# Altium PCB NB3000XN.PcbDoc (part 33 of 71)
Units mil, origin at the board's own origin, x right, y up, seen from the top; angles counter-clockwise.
Board outline 9527.56 x 6929.77 mil, 6 copper layers (Top Layer, GND+SHIELD, MidLayer1, MidLayer2, P2 - 3V3+5V0, Bottom Layer), stack 62.375 mil thick; 832 components, 1027 nets, 4655 pads, 4981 vias.
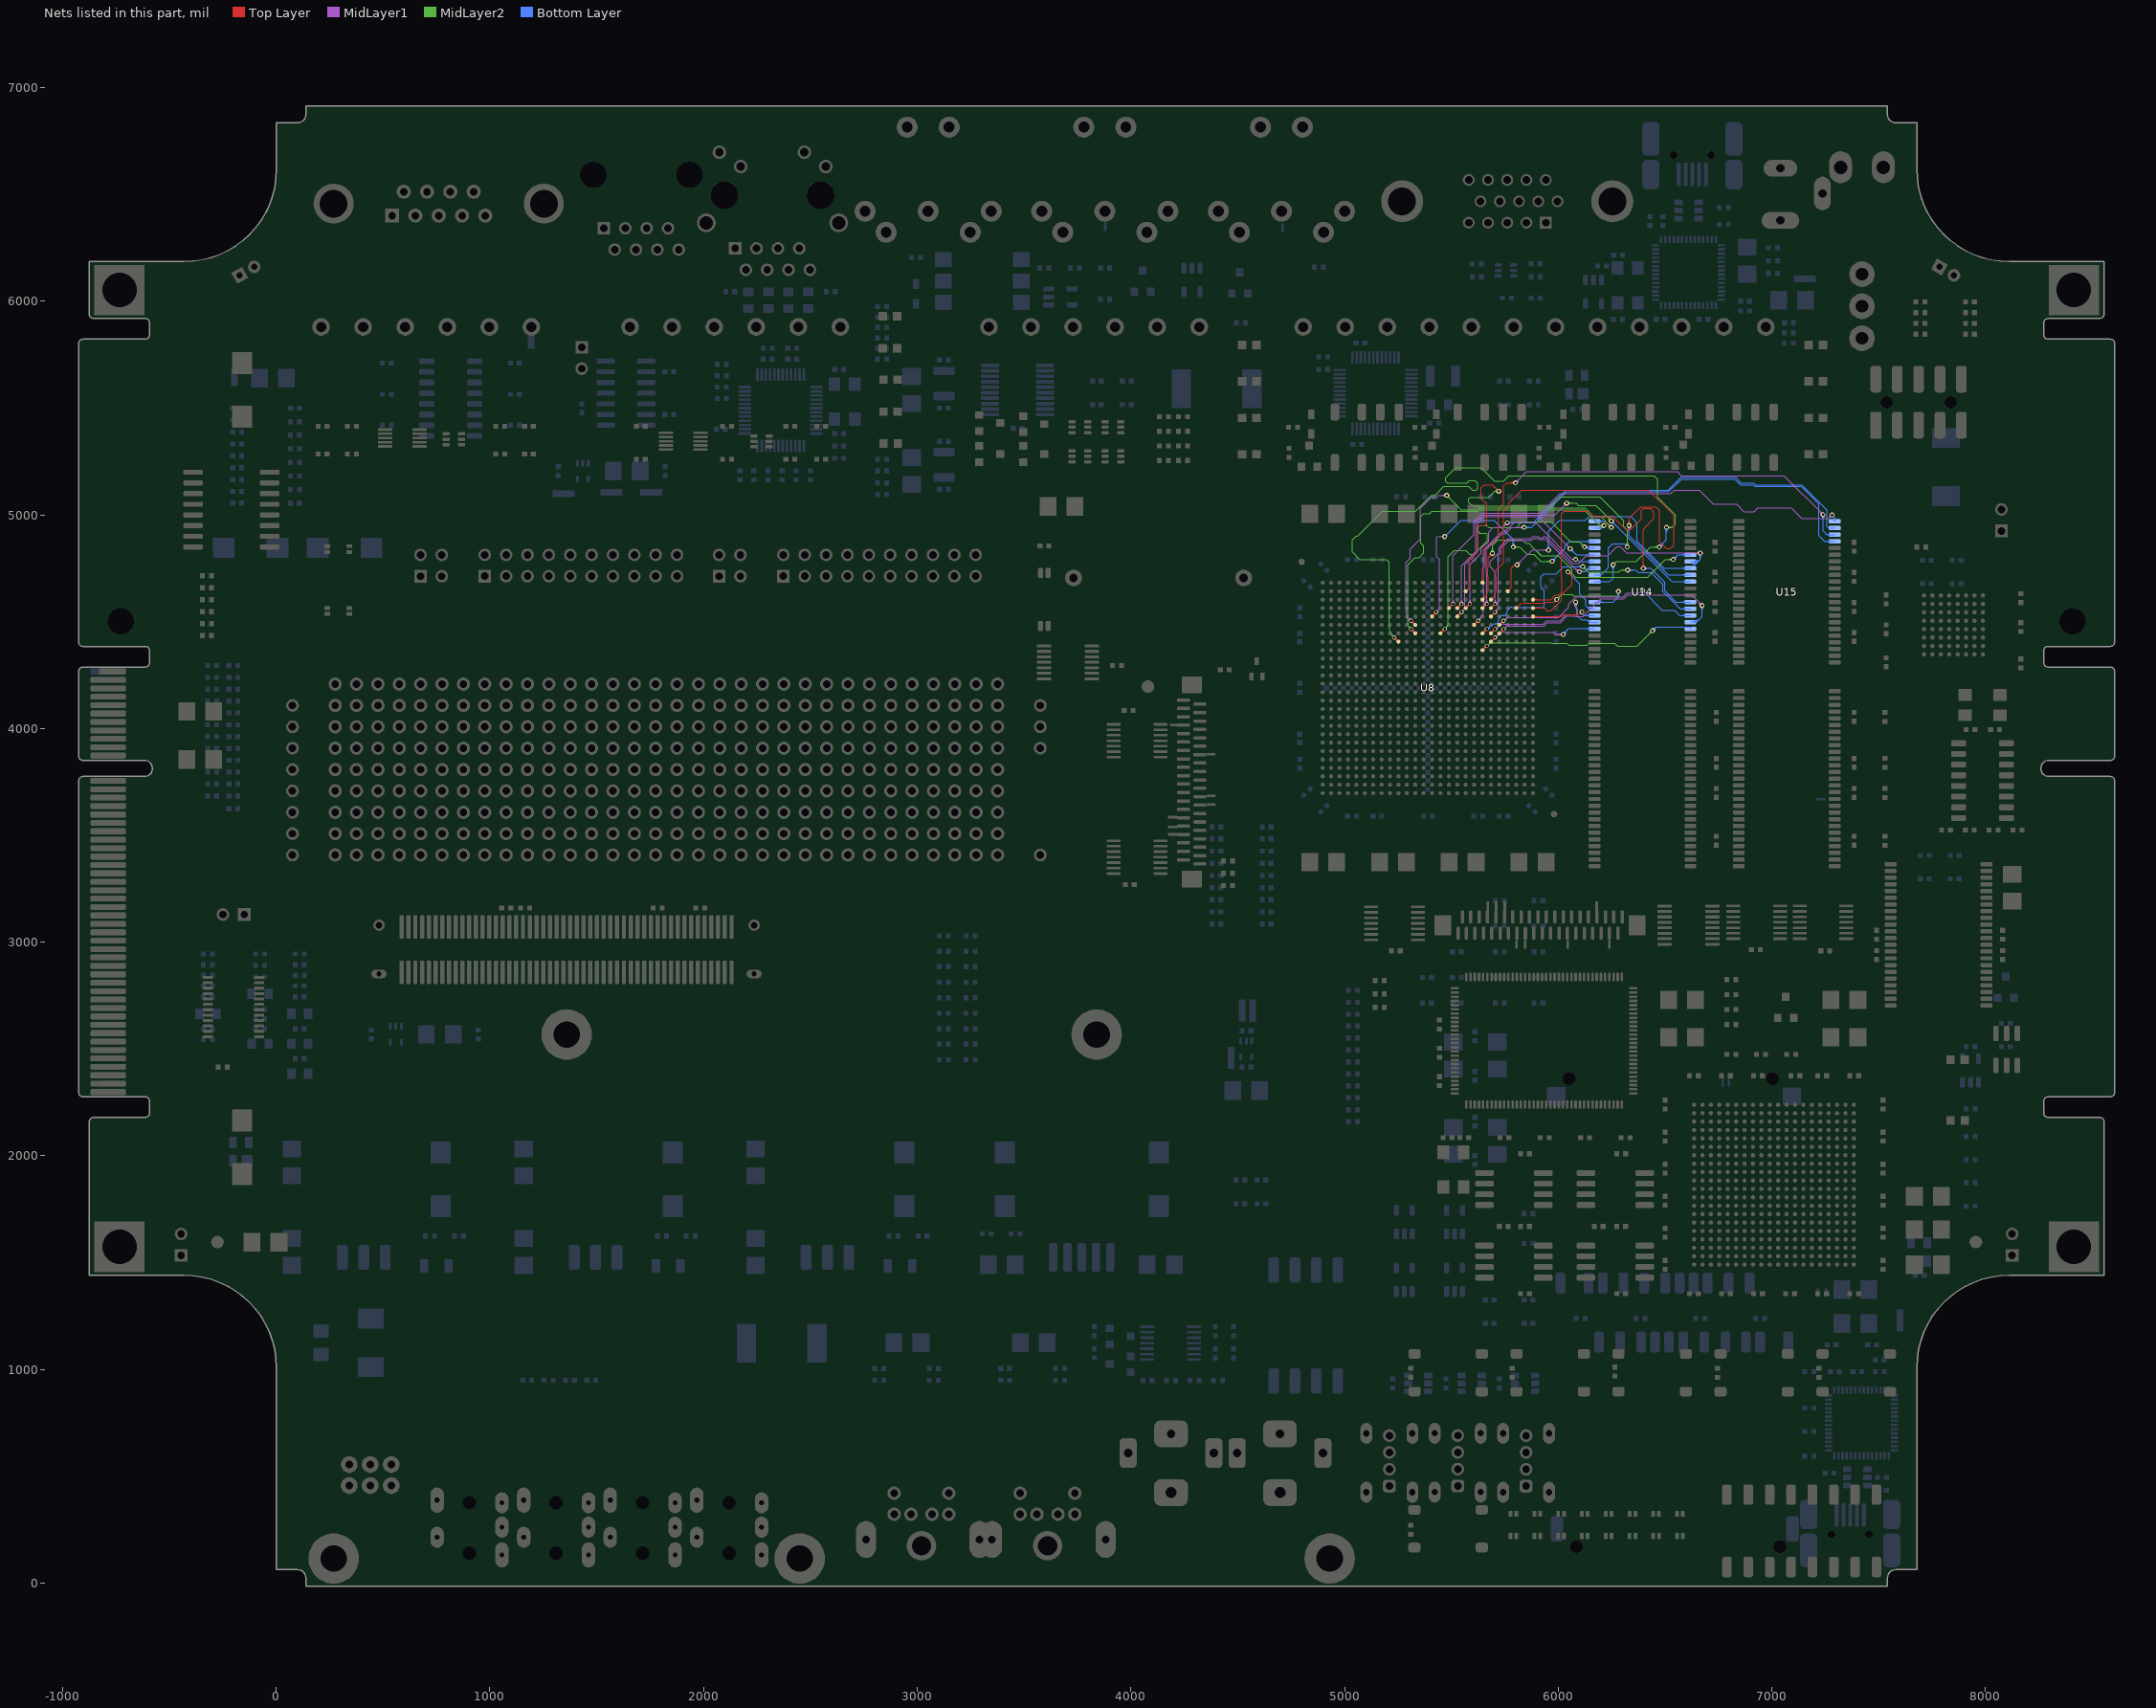
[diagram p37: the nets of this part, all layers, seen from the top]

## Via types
v1: diameter 23, hole 11.81, Top Layer to Bottom Layer, 3672 vias
v2: diameter 26, hole 11.81, Top Layer to Bottom Layer, 461 vias
v3: diameter 19, hole 11.81, Top Layer to Bottom Layer, tented both sides, 396 vias
v4: diameter 23.62, hole 11.81, Top Layer to Bottom Layer, 288 vias
v5: diameter 20, hole 11.81, Top Layer to Bottom Layer, 91 vias
v6: diameter 23, hole 11.81, Top Layer to Bottom Layer, tented both sides, 50 vias
v7: diameter 31, hole 11.81, Top Layer to Bottom Layer, 15 vias
v8: diameter 27.56, hole 11.81, Top Layer to Bottom Layer, tented both sides, 4 vias
v9: diameter 29, hole 11.81, Top Layer to Bottom Layer, 3 vias
v10: diameter 21, hole 11.81, Top Layer to Bottom Layer, 1 vias

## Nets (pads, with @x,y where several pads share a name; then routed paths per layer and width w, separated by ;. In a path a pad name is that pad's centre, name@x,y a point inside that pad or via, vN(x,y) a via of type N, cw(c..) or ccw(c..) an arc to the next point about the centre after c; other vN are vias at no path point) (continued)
DB_SRAM1.A16: U8.G12 U14.43 | length 1799.9
  Top Layer w4: v3(5311.26,4465.59) U8.G12@5330.94,4445.91 ; U8.G12@5323.44,4445.91 ccw(c5305.34,4445.91) 5318.14,4458.71 ccw(c5330.94,4471.51) U8.G12@5330.94,4453.41 ; U8.G12@5323.6,4445.91 ccw(c5305.88,4445.91) 5318.41,4458.44 ccw(c5330.94,4470.97) U8.G12@5330.94,4453.25 ; 5324.06,4452.79 cw(c5336.87,4465.59) 5318.76,4465.59 ccw(c5336.87,4465.59) 5324.06,4452.79 ; 5324.06,4452.79 ccw(c5311.26,4439.98) 5311.26,4458.09 cw(c5311.26,4439.98) 5324.06,4452.79
  MidLayer2 w4: 5295.75,4503.03 5295.75,4489.1 ; 5295.75,4699.16 5295.75,4640.9 ; 5299.87,4479.17 cw(c5309.8,4489.1) 5295.75,4489.1 ; v3@5303.79,4466.24 ccw(c5285.75,4467.82) 5299.62,4479.46 ccw(c5313.49,4491.1) v3@5311.91,4473.06 ; v1@6206.51,4944.45 ccw(c6195.52,4936.45) 6195.52,4950.04 ; v1@6206.51,4955.63 cw(c6195.52,4963.63) 6195.52,4950.04 ; v1(6214.19,4950.04) 6195.52,4950.04 ; 5295.75,4489.1 5295.75,4582.64 5295.75,4640.9 ; 5295.75,4640.9 5295.75,4710 5295.75,4720 5295.75,4766.97 5330,4801.22 5350.04,4801.22 5370.52,4821.71 5370.52,4854.37 5356.86,4868.04 5356.86,4993.04 5370.19,5006.37 5399.19,5006.37 5409.52,5016.71 5625.29,5016.71 5632.78,5024.2 6121.36,5024.2 6195.52,4950.04
  Bottom Layer w4: U14.43@6170.59,4939.21 6203.36,4939.21 ; U14.43@6194.74,4934.68 cw(c6203.36,4928.75) 6203.36,4939.21 ; U14.43@6194.74,4943.74 ccw(c6203.36,4949.67) 6203.36,4939.21 ; v1(6214.19,4950.04) 6203.36,4939.21
DB_SRAM1.A17: U8.F12 U14.44 | length 2061.9
  Top Layer w4: v3(5311.26,4504.96) U8.F12@5330.94,4485.28 ; U8.F12@5323.44,4485.28 ccw(c5305.34,4485.28) 5318.14,4498.08 ccw(c5330.94,4510.88) U8.F12@5330.94,4492.78 ; U8.F12@5323.6,4485.28 ccw(c5305.88,4485.28) 5318.41,4497.81 ccw(c5330.94,4510.34) U8.F12@5330.94,4492.62 ; 5324.06,4492.16 cw(c5336.87,4504.96) 5318.76,4504.96 ccw(c5336.87,4504.96) 5324.06,4492.16 ; 5324.06,4492.16 ccw(c5311.26,4479.35) 5311.26,4497.46 cw(c5311.26,4479.35) 5324.06,4492.16
  MidLayer1 w4: 5287.4,4581.77 5287.4,4567.84 ; v3@5303.79,4505.61 ccw(c5285.75,4507.19) 5299.62,4518.83 ; v3@5311.91,4512.43 cw(c5313.49,4530.47) 5299.62,4518.83 ; v1@5471.47,5084.99 ccw(c5455.26,5068.77) 5455.26,5091.71 ccw(c5455.26,5114.64) v1@5471.47,5098.43 ; v1@5474.3,5087.82 ccw(c5464.91,5078.43) 5464.91,5091.71 ccw(c5464.91,5104.99) v1@5474.3,5095.6 ; v1(5478.19,5091.71) 5438.33,5091.71 5430,5083.37 5406.52,5083.37 5354.86,5031.71 5354.86,4888.04 5306.86,4840.04 5306.86,4797.02 5287.4,4777.56 5287.4,4720 5287.4,4710 5287.4,4661.38 5287.4,4641.96 5287.4,4567.84 ; 5287.4,4567.84 5287.4,4548.34 ccw(c5329.13,4548.34) 5299.62,4518.83
  MidLayer2 w4: v1@5478.19,5082.21 cw(c5478.19,5059.27) 5494.41,5075.49 cw(c5510.63,5091.71) v1@5487.69,5091.71 ; v1@5478.19,5086.21 cw(c5478.19,5072.93) 5487.58,5082.32 cw(c5496.97,5091.71) v1@5483.69,5091.71 ; v1(5478.19,5091.71) 5544.86,5025.04 5622.31,5025.04 5629.47,5032.2 6124.69,5032.2 6165.19,4991.71 6198.52,4991.71 v1(6248.52,4941.71) ; v1@6239.02,4941.71 ccw(c6216.09,4941.71) 6232.31,4957.93 ccw(c6248.52,4974.14) v1@6248.52,4951.21 ; v1@6243.02,4941.71 ccw(c6229.75,4941.71) 6239.14,4951.1 ccw(c6248.52,4960.49) v1@6248.52,4947.21
  Bottom Layer w4: U14.44@6170.59,4970.71 6219.53,4970.71 v1(6248.52,4941.71) ; U14.44@6193.81,4965.05 cw(c6207.46,4951.4) 6207.46,4970.71 cw(c6207.47,4990.02) U14.44@6193.81,4976.36 ; v1@6239.02,4941.71 ccw(c6216.09,4941.71) 6232.31,4957.93 ccw(c6248.52,4974.14) v1@6248.52,4951.21 ; v1@6243.02,4941.71 ccw(c6229.75,4941.71) 6239.14,4951.1 ccw(c6248.52,4960.49) v1@6248.52,4947.21
DB_SRAM1.A18: U8.H21 U14.28 | length 811.3
  Top Layer w4: U8.H21@5685.28,4406.54 v3(5704.96,4426.22) ; U8.H21@5685.28,4413.88 ccw(c5685.28,4431.6) 5697.81,4419.07 ccw(c5710.34,4406.54) U8.H21@5692.62,4406.54 ; U8.H21@5685.28,4414.04 ccw(c5685.28,4432.14) 5698.08,4419.34 ccw(c5710.88,4406.54) U8.H21@5692.78,4406.54 ; 5692.16,4413.42 cw(c5704.96,4400.61) 5704.96,4418.72 ccw(c5704.96,4400.61) 5692.16,4413.42 ; 5692.16,4413.42 ccw(c5679.35,4426.22) 5697.46,4426.22 cw(c5679.35,4426.22) 5692.16,4413.42
  MidLayer1 w4: v3@5705.61,4433.69 ccw(c5707.19,4451.73) 5718.83,4437.86 ; v3@5712.43,4425.57 cw(c5730.47,4423.99) 5718.83,4437.86 ; 5781.77,4450.08 5767.84,4450.08 ; 5923.52,4450.04 5980,4450.04 5989.33,4440.71 v1(6023.52,4440.71) ; 5923.52,4450.08 5924.74,4450.08 5920,4450.08 5910,4450.08 5861.38,4450.08 5841.96,4450.08 5767.84,4450.08 ; v1@6016.81,4433.99 ccw(c6000.59,4417.77) 6000.59,4440.71 ccw(c6000.59,4463.64) v1@6016.81,4447.43 ; v1@6019.64,4436.82 ccw(c6010.25,4427.43) 6010.25,4440.71 ccw(c6010.25,4453.99) v1@6019.64,4444.6 ; 5718.83,4437.86 cw(c5748.34,4408.35) 5748.34,4450.08 5767.84,4450.08
  Bottom Layer w4: v1(6023.52,4440.71) 6023.52,4441.71 6049.52,4467.71 6164.52,4467.71 6165.19,4467.04 6165.19,4466.77 U14.28@6170.59,4466.77 ; v1@6023.52,4446.21 ccw(c6023.52,4457.07) 6031.21,4449.39 ; v1@6023.52,4450.21 ccw(c6023.52,4470.73) 6038.03,4456.22 ; v1@6029.02,4440.71 cw(c6044.72,4440.71) 6033.62,4451.8 ; v1@6033.02,4440.71 cw(c6058.37,4440.71) 6040.45,4458.63 ; 6131.46,4467.71 cw(c6131.46,4445.19) U14.28@6147.37,4461.11 ; 6135.98,4467.71 ccw(c6135.98,4483.82) U14.28@6147.37,4472.43 ; 6141.11,4467.71 cw(c6141.11,4454.85) U14.28@6150.2,4463.94
DB_SRAM1.D0: U8.D21 U14.7 | length 1913.9
  Top Layer w4: U8.D21@5685.28,4564.02 v3(5704.96,4583.7) ; U8.D21@5685.28,4571.36 ccw(c5685.28,4589.08) 5697.81,4576.55 ccw(c5710.34,4564.02) U8.D21@5692.62,4564.02 ; U8.D21@5685.28,4571.52 ccw(c5685.28,4589.62) 5698.08,4576.82 ccw(c5710.88,4564.02) U8.D21@5692.78,4564.02 ; 5692.16,4570.9 cw(c5704.96,4558.09) 5704.96,4576.2 ccw(c5704.96,4558.09) 5692.16,4570.9 ; 5692.16,4570.9 ccw(c5679.35,4583.7) 5697.46,4583.7 cw(c5679.35,4583.7) 5692.16,4570.9
  MidLayer1 w4: v3@5699.77,4588.89 ccw(c5687.23,4601.43) 5704.96,4601.43 ccw(c5722.69,4601.43) v3@5710.15,4588.89 ; v3(5704.96,4583.7) 5704.96,4661.38 5704.96,4710 5704.96,4720 5704.96,4733.27 5680.86,4757.37 5680.86,4782.37 5723.52,4825.04 5723.52,4847.04 5765.19,4888.71 5872.19,4888.71 5881.86,4898.37 5906.88,4898.37 5912.75,4892.5 5927.25,4892.5 5933.12,4898.37 5941.86,4898.37 6066.19,4774.04 6096.86,4774.04 6131.19,4808.37 6231.86,4808.37 6274.36,4850.87 6290.36,4850.87 6319.52,4821.71 v1(6665.19,4821.71) ; v1@6658.47,4814.99 ccw(c6642.26,4798.77) 6642.26,4821.71 ccw(c6642.26,4844.64) v1@6658.47,4828.43 ; v1@6661.3,4817.82 ccw(c6651.91,4808.43) 6651.91,4821.71 ccw(c6651.91,4834.99) v1@6661.3,4825.6 ; 5704.96,4601.81 cw(c5686.85,4601.81) 5699.66,4589 ccw(c5686.85,4601.81) 5704.96,4601.81 ; 5704.96,4601.81 ccw(c5723.07,4601.81) 5710.26,4589 cw(c5723.07,4601.81) 5704.96,4601.81
  Bottom Layer w4: U14.7@6619.41,4781.73 U14.7@6636.96,4781.73 ; 6630.88,4771.39 ccw(c6637.58,4782.77) 6646.92,4773.43 ; U14.7@6632.91,4774.84 ccw(c6640.29,4787.37) 6650.57,4777.09 ; U14.7@6634.94,4778.28 ccw(c6642.99,4791.97) 6654.23,4780.74 ; U14.7@6639,4785.18 ccw(c6648.41,4801.18) 6661.54,4788.05 ; U14.7@6641.02,4788.63 ccw(c6651.12,4805.78) 6665.19,4791.71 ; 6657.88,4784.4 cw(c6645.7,4796.58) U14.7@6636.97,4781.73 ; v1@6658.47,4814.99 cw(c6642.26,4798.77) 6665.19,4798.77 cw(c6688.13,4798.77) v1@6671.91,4814.99 ; v1@6661.3,4817.82 cw(c6651.91,4808.43) 6665.19,4808.43 cw(c6678.47,4808.43) v1@6669.08,4817.82 ; v1(6665.19,4821.71) 6665.19,4791.71 ; U14.7@6636.96,4781.73 6636.96,4775.04 6648.52,4775.04 6665.19,4791.71
DB_SRAM1.D1: U8.B23 U14.8 | length 1596.8
  Top Layer w4: 5780.47,4750.47 cw(c5806.45,4724.49) v1@5807.67,4761.21 ; 5786.99,4756.99 cw(c5806.87,4737.11) v1@5807.81,4765.21 ; 5793.51,4763.51 cw(c5807.29,4749.72) v1@5807.94,4769.21 ; v1(5807.86,4766.71) 5796.71,4766.71 5779.52,4749.52 5779.52,4720 5779.52,4710 5779.52,4662.47 ; 5776.55,4655.29 ccw(c5769.37,4662.47) 5779.52,4662.47 ; 5776.55,4655.29 ccw(c5769.37,4662.47) 5779.52,4662.47 ; 5776.55,4655.29 cw(c5764.02,4667.83) 5764.02,4650.1 ccw(c5764.02,4667.83) 5776.55,4655.29 ; 5776.55,4655.29 ccw(c5789.08,4642.76) 5771.36,4642.76 cw(c5789.08,4642.76) 5776.55,4655.29
  MidLayer1 w4: v1(5807.86,4766.71) 5856.15,4815 5860,4815 5880,4835 v1(5955,4835) 5955,4835.23 v1@5948.52,4841.71 ; v1@5807.86,4772.21 ccw(c5807.86,4785.49) 5817.25,4776.1 ccw(c5826.64,4766.71) v1@5813.36,4766.71 ; v1@5807.86,4776.21 ccw(c5807.86,4799.14) 5824.07,4782.93 ccw(c5840.29,4766.71) v1@5817.36,4766.71 ; v1@5948.28,4828.28 ccw(c5932.06,4812.06) 5932.06,4835 ccw(c5932.06,4857.93) v1@5948.28,4841.72 ; v1@5951.11,4831.11 ccw(c5941.72,4821.72) 5941.72,4835 ccw(c5941.72,4848.28) v1@5951.11,4838.89
  Bottom Layer w4: v1@5948.28,4841.72 ccw(c5932.06,4857.93) 5955,4857.93 ccw(c5977.93,4857.93) v1@5961.72,4841.72 ; v1@5948.52,4841.48 v1(5955,4835) 5955,4923.18 5996.38,4964.57 ; v1@5951.11,4838.89 ccw(c5941.72,4848.28) 5955,4848.28 ccw(c5968.28,4848.28) v1@5958.89,4838.89 ; 6001.11,4969.29 5996.38,4964.57 ; 6340.52,4991.71 6340,4991.71 ; 6506.52,4750.37 6506.52,4750.23 ; U14.8@6596.19,4744.58 ccw(c6582.54,4730.92) 6582.54,4750.23 ccw(c6582.54,4769.55) U14.8@6596.19,4755.89 ; U14.8@6619.41,4750.23 6506.52,4750.23 ; 5996.38,4964.57 6006.86,4975.04 6128.19,4975.04 6144.86,4991.71 6340,4991.71 ; 6340,4991.71 6370,4961.71 6370,4875.91 6495.67,4750.23 6506.52,4750.23
DB_SRAM1.D2: U8.C21 U14.9 | length 2701.3
  Top Layer w4: 5743.52,4821.71 5743.52,4822 ; v1@6325.14,4957.09 ccw(c6308.92,4973.31) 6331.86,4973.31 ccw(c6354.79,4973.31) v1@6338.57,4957.09 ; v1@6327.97,4954.26 ccw(c6318.58,4963.65) 6331.86,4963.65 ccw(c6345.14,4963.65) v1@6335.75,4954.26 ; v1(6331.86,4950.37) 6331.86,4983.37 6354.52,5006.04 6386.52,5038.04 6456.86,5038.04 6473.52,5021.37 6473.52,4875.04 6506.86,4841.71 6524.86,4841.71 6541.52,4858.37 6541.52,4998.71 6423.52,5116.71 5829.86,5116.71 5769,5055.85 5769,5042.24 5743.52,5016.77 5743.52,4822 ; 5697.81,4615.92 ccw(c5670.46,4643.27) 5709.14,4643.27 ; 5697.81,4615.92 ccw(c5670.46,4643.27) 5709.14,4643.27 ; 5697.81,4615.92 ccw(c5710.34,4603.39) 5692.62,4603.39 cw(c5710.34,4603.39) 5697.81,4615.92 ; 5697.81,4615.92 cw(c5685.28,4628.45) 5685.28,4610.73 ccw(c5685.28,4628.45) 5697.81,4615.92 ; 5709.14,4643.27 5709.14,4710 5709.14,4720 5709.14,4724.74 5709.14,4741.01 5743.52,4775.39 5743.52,4822
  Bottom Layer w4: v1@6325.14,4943.66 cw(c6308.92,4927.44) 6331.86,4927.44 cw(c6354.79,4927.44) v1@6338.57,4943.66 ; v1@6327.97,4946.49 cw(c6318.58,4937.1) 6331.86,4937.1 cw(c6345.14,4937.1) v1@6335.75,4946.49 ; v1(6331.86,4950.37) 6331.86,4902.74 6475.23,4759.36 6515.86,4718.74 ; 6493.52,4741.07 6515.86,4718.74 ; 6515.86,4718.74 U14.9@6619.41,4718.74 6515.86,4718.74 ; 6582.54,4718.74 cw(c6582.54,4699.42) 6596.19,4713.08 ccw(c6582.54,4699.42) 6582.54,4718.74 ; 6582.54,4718.74 ccw(c6582.54,4738.05) 6596.19,4724.4 cw(c6582.54,4738.05) 6582.54,4718.74
DB_SRAM1.D3: U8.D17 U14.10 | length 2087.1
  Top Layer w4: U8.D17@5527.8,4564.02 v3(5547.48,4583.7) ; U8.D17@5527.8,4571.36 ccw(c5527.8,4589.08) 5540.33,4576.55 ccw(c5552.86,4564.02) U8.D17@5535.14,4564.02 ; U8.D17@5527.8,4571.52 ccw(c5527.8,4589.62) 5540.6,4576.82 ccw(c5553.4,4564.02) U8.D17@5535.3,4564.02 ; 5534.68,4570.9 cw(c5547.48,4558.09) 5547.48,4576.2 ccw(c5547.48,4558.09) 5534.68,4570.9 ; 5534.68,4570.9 ccw(c5521.87,4583.7) 5539.98,4583.7 cw(c5521.87,4583.7) 5534.68,4570.9
  MidLayer1 w4: v3@5542.29,4588.89 ccw(c5529.75,4601.43) 5547.48,4601.43 ccw(c5565.21,4601.43) v3@5552.67,4588.89 ; v3(5547.48,4583.7) 5547.48,4661.38 5547.48,4710 5547.48,4720 5547.48,4724.74 5547.48,4752.37 5547.48,4762.46 5615.02,4830 5615.02,4965.33 5649.74,5000.04 5985.04,5000.04 v1(6040,5055) ; v1@6030.5,5055 cw(c6007.56,5055) 6023.78,5038.78 cw(c6040,5022.56) v1@6040,5045.5 ; v1@6034.5,5055 cw(c6021.22,5055) 6030.61,5045.61 cw(c6040,5036.22) v1@6040,5049.5 ; 5547.48,4601.81 cw(c5529.37,4601.81) 5542.18,4589 ccw(c5529.37,4601.81) 5547.48,4601.81 ; 5547.48,4601.81 ccw(c5565.59,4601.81) 5552.78,4589 cw(c5565.59,4601.81) 5547.48,4601.81
  MidLayer2 w4: v1(6040,5055) 6084.37,5055 6095,5044.37 6175.86,5044.37 v1(6248.52,4971.71) ; v1@6043.89,5051.11 cw(c6053.28,5041.72) 6053.28,5055 cw(c6053.28,5068.28) v1@6043.89,5058.89 ; v1@6046.72,5048.28 cw(c6062.93,5032.06) 6062.93,5055 cw(c6062.93,5077.93) v1@6046.72,5061.72 ; v1@6239.02,4971.71 ccw(c6216.09,4971.71) 6232.31,4987.93 ccw(c6248.52,5004.14) v1@6248.52,4981.21 ; v1@6243.02,4971.71 ccw(c6229.75,4971.71) 6239.14,4981.1 ccw(c6248.52,4990.49) v1@6248.52,4977.21
  Bottom Layer w4: v1@6248.52,4962.21 cw(c6248.52,4939.27) 6264.74,4955.49 cw(c6280.96,4971.71) v1@6258.02,4971.71 ; v1@6248.52,4966.21 cw(c6248.52,4952.93) 6257.91,4962.32 cw(c6267.3,4971.71) v1@6254.02,4971.71 ; v1(6248.52,4971.71) 6465.19,4755.04 6532.99,4687.24 U14.10@6619.41,4687.24 ; U14.10@6596.19,4681.59 ccw(c6582.54,4667.93) 6582.54,4687.24 ccw(c6582.54,4706.56) U14.10@6596.19,4692.9
DB_SRAM1.D4: U8.C26 U14.13 | length 1855
  Top Layer w4: U8.C26@5882.13,4603.39 5910,4603.39 5920,4603.39 5924.74,4603.39 5965.87,4603.39 5987.52,4625.04 6003.19,4625.04 6018.19,4640.04 6018.19,4700.04 6015.19,4703.04 6015.19,5005.19 6027.04,5017.04 6139.67,5017.04 6165,4991.71 6255.52,4991.71 6315.19,4932.04 6340.19,4932.04 6390.19,4982.04 6390.19,5021.71 6398.52,5030.04 6431.86,5030.04 6448.52,5013.37 6448.52,4983.37 6398.52,4933.37 v1(6398.52,4750.04) ; U8.C26@5887.32,4598.19 cw(c5899.85,4585.66) 5899.85,4603.39 cw(c5899.85,4621.11) U8.C26@5887.32,4608.58 ; U8.C26@5887.43,4598.08 cw(c5900.23,4585.28) 5900.23,4603.39 cw(c5900.23,4621.49) U8.C26@5887.43,4608.69 ; v1@6391.81,4756.76 ccw(c6375.59,4772.98) 6398.52,4772.98 ccw(c6421.46,4772.98) v1@6405.24,4756.76 ; v1@6394.64,4753.93 ccw(c6385.25,4763.32) 6398.52,4763.32 ccw(c6411.8,4763.32) v1@6402.41,4753.93
  Bottom Layer w4: v1(6398.52,4750.04) 6431.86,4750.04 6498.52,4683.37 6498.52,4644.69 6550.46,4592.75 U14.13@6619.41,4592.75 ; v1@6402.41,4746.15 cw(c6411.8,4736.76) 6411.8,4750.04 cw(c6411.8,4763.32) v1@6402.41,4753.93 ; v1@6405.24,4743.32 cw(c6421.46,4727.11) 6421.46,4750.04 cw(c6421.46,4772.98) v1@6405.24,4756.76 ; U14.13@6596.19,4587.1 ccw(c6582.54,4573.44) 6582.54,4592.75 ccw(c6582.54,4612.07) U14.13@6596.19,4598.41
DB_SRAM1.D5: U8.G20 U14.14 | length 1710.9
  Top Layer w4: U8.G20@5645.91,4445.91 v3(5665.59,4465.59) ; U8.G20@5645.91,4453.25 ccw(c5645.91,4470.97) 5658.44,4458.44 ccw(c5670.97,4445.91) U8.G20@5653.25,4445.91 ; U8.G20@5645.91,4453.41 ccw(c5645.91,4471.51) 5658.71,4458.71 ccw(c5671.51,4445.91) U8.G20@5653.41,4445.91 ; 5652.79,4452.79 cw(c5665.59,4439.98) 5665.59,4458.09 ccw(c5665.59,4439.98) 5652.79,4452.79 ; 5652.79,4452.79 ccw(c5639.98,4465.59) 5658.09,4465.59 cw(c5639.98,4465.59) 5652.79,4452.79
  MidLayer2 w4: v1@6115.19,4748.87 cw(c6115.19,4725.94) 6131.41,4742.16 cw(c6147.63,4758.37) v1@6124.69,4758.37 ; v1@6115.19,4752.87 cw(c6115.19,4739.6) 6124.58,4748.99 cw(c6133.97,4758.37) v1@6120.69,4758.37 ; v1(6115.19,4758.37) 6140.19,4733.37 6285,4733.37 6293.33,4741.71 v1(6325.19,4741.71) ; v1@6318.47,4734.99 ccw(c6302.26,4718.77) 6302.26,4741.71 ccw(c6302.26,4764.64) v1@6318.47,4748.43 ; v1@6321.3,4737.82 ccw(c6311.91,4728.43) 6311.91,4741.71 ccw(c6311.91,4754.99) v1@6321.3,4745.6
  Bottom Layer w4: v3@5666.89,4472.98 ccw(c5670.04,4490.81) 5680.42,4475.98 ; v3@5672.98,4464.29 cw(c5690.81,4461.14) 5680.42,4475.98 ; 5920,4658.43 5922.22,4656.22 ; v1@6108.47,4751.66 ccw(c6092.26,4735.44) 6092.26,4758.37 ccw(c6092.26,4781.31) v1@6108.47,4765.09 ; v1@6111.3,4754.49 ccw(c6101.91,4745.1) 6101.91,4758.37 ccw(c6101.91,4771.65) v1@6111.3,4762.26 ; v1(6115.19,4758.37) 6023.52,4758.37 5990.19,4725.04 5932.19,4725.04 5918.48,4711.33 5918.48,4659.96 5922.22,4656.22 ; v1(6325.19,4741.71) 6363.29,4741.71 6375,4730 6435.23,4730 6456.52,4708.71 6490.19,4675.04 6490.19,4641.71 6570.64,4561.26 U14.14@6619.41,4561.26 ; v1@6329.08,4737.82 cw(c6338.47,4728.43) 6338.47,4741.71 cw(c6338.47,4754.99) v1@6329.08,4745.6 ; v1@6331.91,4734.99 cw(c6348.13,4718.77) 6348.13,4741.71 cw(c6348.13,4764.64) v1@6331.91,4748.43 ; U14.14@6596.19,4555.6 ccw(c6582.54,4541.94) 6582.54,4561.26 ccw(c6582.54,4580.57) U14.14@6596.19,4566.92 ; 5680.42,4475.98 5688.15,4482.4 cw(c5704.96,4465.59) 5704.96,4489.36 ccw(c5704.96,4504.96) 5720.56,4504.96 cw(c5744.33,4504.96) 5744.33,4528.73 ccw(c5744.33,4544.33) 5759.93,4544.33 cw(c5783.7,4544.33) 5783.7,4568.1 5841.96,4568.1 5900.22,4568.1 5910,4568.1 5920,4568.1 5924.74,4568.1 5931.86,4568.1 5935,4571.24 5935,4643.43 5922.22,4656.22
DB_SRAM1.D6: U8.F22 U14.15 | length 1228.3
  Top Layer w4: U8.F22@5724.65,4485.28 v3(5744.33,4504.96) ; U8.F22@5724.65,4492.62 ccw(c5724.65,4510.34) 5737.18,4497.81 ccw(c5749.71,4485.28) U8.F22@5731.99,4485.28 ; U8.F22@5724.65,4492.78 ccw(c5724.65,4510.88) 5737.45,4498.08 ccw(c5750.25,4485.28) U8.F22@5732.15,4485.28 ; 5731.53,4492.16 cw(c5744.33,4479.35) 5744.33,4497.46 ccw(c5744.33,4479.35) 5731.53,4492.16 ; 5731.53,4492.16 ccw(c5718.72,4504.96) 5736.83,4504.96 cw(c5718.72,4504.96) 5731.53,4492.16
  MidLayer1 w4: v3@5745.63,4512.35 ccw(c5748.78,4530.18) 5759.16,4515.35 ccw(c5769.55,4500.51) v3@5751.72,4503.66 ; 5759.19,4515.38 cw(c5776.84,4487.34) 5777.01,4520.47 5861.38,4520.47 5910,4520.47 ; 5910,4520.54 5920,4520.54 6001.75,4520.54 6040.63,4559.42 6041.23,4559.42 6048.52,4566.71 6048.52,4583.37 6081.86,4616.71 6303.88,4616.71 6320.88,4633.71 6382.19,4633.71 v1(6395.19,4646.71)
  Bottom Layer w4: v1@6395.19,4637.21 cw(c6395.19,4614.27) 6411.41,4630.49 cw(c6427.63,4646.71) v1@6404.69,4646.71 ; v1@6395.19,4641.21 cw(c6395.19,4627.93) 6404.58,4637.32 cw(c6413.97,4646.71) v1@6400.69,4646.71 ; v1(6395.19,4646.71) 6486.9,4555 6544.53,4555 6569.76,4529.76 U14.15@6619.41,4529.76 ; U14.15@6596.19,4524.11 ccw(c6582.54,4510.45) 6582.54,4529.76 ccw(c6582.54,4549.08) U14.15@6596.19,4535.42
DB_SRAM1.D7: U8.G22 U14.16 | length 1487.7
  Top Layer w4: U8.G22@5724.65,4445.91 v3(5744.33,4465.59) ; U8.G22@5724.65,4453.25 ccw(c5724.65,4470.97) 5737.18,4458.44 ccw(c5749.71,4445.91) U8.G22@5731.99,4445.91 ; U8.G22@5724.65,4453.41 ccw(c5724.65,4471.51) 5737.45,4458.71 ccw(c5750.25,4445.91) U8.G22@5732.15,4445.91 ; 5731.53,4452.79 cw(c5744.33,4439.98) 5744.33,4458.09 ccw(c5744.33,4439.98) 5731.53,4452.79 ; 5731.53,4452.79 ccw(c5718.72,4465.59) 5736.83,4465.59 cw(c5718.72,4465.59) 5731.53,4452.79
  MidLayer1 w4: v3@5744.98,4473.06 ccw(c5746.56,4491.1) 5758.2,4477.23 ccw(c5769.84,4463.36) v3@5751.8,4464.94 ; 5757.91,4476.99 cw(c5767.84,4467.05) 5767.84,4481.1 5861.38,4481.1 5933.83,4481.1 5949.28,4496.54 6011.69,4496.54 6041.19,4526.04 6079.21,4526.04 6080.04,4525.21 6115.36,4525.21 6198.52,4608.37 6306.86,4608.37 6324.19,4625.71 6623.86,4625.71 v1(6673.52,4576.04) ; v1@6664.02,4576.04 ccw(c6641.09,4576.04) 6657.31,4592.26 ccw(c6673.52,4608.48) v1@6673.52,4585.54 ; v1@6668.02,4576.04 ccw(c6654.75,4576.04) 6664.14,4585.43 ccw(c6673.52,4594.82) v1@6673.52,4581.54
  Bottom Layer w4: U14.16@6619.41,4498.27 6623.52,4498.27 6623.52,4500.04 6648.52,4500.04 ; U14.16@6636.97,4498.27 ccw(c6636.97,4521.88) 6653.67,4505.18 ; U14.16@6636.97,4502.27 ccw(c6636.97,4535.54) 6660.5,4512.01 ; U14.16@6636.97,4506.27 ccw(c6636.97,4549.2) 6667.32,4518.84 ; U14.16@6643.65,4502.67 ccw(c6648.52,4505.88) 6648.52,4500.04 ; U14.16@6644.86,4496.94 cw(c6648.52,4496.32) 6648.52,4500.04 ; v1@6666.81,4569.32 cw(c6650.59,4553.11) 6673.52,4553.11 cw(c6696.46,4553.11) v1@6680.24,4569.32 ; v1@6669.64,4572.15 cw(c6660.25,4562.76) 6673.52,4562.76 cw(c6686.8,4562.76) v1@6677.41,4572.15 ; v1(6673.52,4576.04) 6673.52,4525.04 6648.52,4500.04
DB_SRAM1.D8: U8.G21 U14.29 | length 1019
  Top Layer w4: U8.G21@5685.28,4445.91 v3(5704.96,4465.59) ; U8.G21@5685.28,4453.25 ccw(c5685.28,4470.97) 5697.81,4458.44 ccw(c5710.34,4445.91) U8.G21@5692.62,4445.91 ; U8.G21@5685.28,4453.41 ccw(c5685.28,4471.51) 5698.08,4458.71 ccw(c5710.88,4445.91) U8.G21@5692.78,4445.91 ; 5692.16,4452.79 cw(c5704.96,4439.98) 5704.96,4458.09 ccw(c5704.96,4439.98) 5692.16,4452.79 ; 5692.16,4452.79 ccw(c5679.35,4465.59) 5697.46,4465.59 cw(c5679.35,4465.59) 5692.16,4452.79
  MidLayer1 w4: v3@5706.26,4472.98 ccw(c5709.41,4490.81) 5719.79,4475.98 ; v3@5712.35,4464.29 cw(c5730.18,4461.14) 5719.79,4475.98 ; 5781.77,4489.45 5767.84,4489.45 ; v1(6081.86,4591.71) 6081.86,4568.33 6090.19,4560 6090.19,4541.71 6082.52,4534.04 6037.88,4534.04 6008.38,4504.54 5945.02,4504.54 5929.94,4489.45 5920,4489.45 5910,4489.45 5861.38,4489.45 5841.96,4489.45 5767.84,4489.45 ; 5719.79,4475.98 5728.37,4483.06 cw(c5744.59,4465.68) 5744.42,4489.45 ; 5744.42,4489.45 cw(c5744.59,4465.68) 5744.59,4489.45 ; 5744.42,4489.45 5744.59,4489.45 ; 5744.59,4489.45 5767.84,4489.45 ; 6081.86,4568.77 cw(c6104.79,4568.77) 6088.57,4584.99 ccw(c6104.79,4568.77) 6081.86,4568.77 ; 6081.86,4568.77 ccw(c6058.92,4568.77) 6075.14,4584.99 cw(c6058.92,4568.77) 6081.86,4568.77 ; 6081.86,4578.43 cw(c6095.14,4578.43) 6085.75,4587.82 ccw(c6095.14,4578.43) 6081.86,4578.43 ; 6081.86,4578.43 ccw(c6068.58,4578.43) 6077.97,4587.82 cw(c6068.58,4578.43) 6081.86,4578.43
  Bottom Layer w4: v1@6075.14,4584.99 cw(c6058.92,4568.77) 6081.86,4568.77 cw(c6104.79,4568.77) v1@6088.57,4584.99 ; v1@6077.97,4587.82 cw(c6068.58,4578.43) 6081.86,4578.43 cw(c6095.14,4578.43) v1@6085.75,4587.82 ; v1(6081.86,4591.71) 6081.86,4563.33 6090.19,4555 6090.19,4526.71 6108.52,4508.37 6135,4508.37 6145.11,4498.27 U14.29@6150,4498.27 ; 6138.96,4504.41 ccw(c6143.43,4508.88) U14.29@6147.66,4504.2 ; 6141.93,4501.44 ccw(c6146.25,4505.76) U14.29@6150.35,4501.23 ; U14.29@6167.89,4498.27 U14.29@6150,4498.27 ; U14.29@6188.27,4498.27 U14.29@6150,4498.27
DB_SRAM1.D9: U8.E26 U14.30 | length 407.5
  Top Layer w4: U8.E26@5882.13,4524.65 5910,4524.65 5920,4524.65 6015,4524.65 6023.73,4533.37 6098.52,4533.37 v1(6111.19,4546.04) ; U8.E26@5887.32,4519.45 cw(c5899.85,4506.92) 5899.85,4524.65 cw(c5899.85,4542.37) U8.E26@5887.32,4529.84 ; U8.E26@5887.43,4519.34 cw(c5900.23,4506.54) 5900.23,4524.65 cw(c5900.23,4542.75) U8.E26@5887.43,4529.95
  Bottom Layer w4: v1(6111.19,4546.04) 6102.86,4546.04 6103.25,4545.65 6103.25,4545.43 6106.91,4541.76 6118.91,4529.76 U14.30@6170.59,4529.76 ; U14.30@6147.37,4524.11 ccw(c6133.72,4510.45) 6133.72,4529.76 ccw(c6133.72,4549.08) U14.30@6147.37,4535.42
DB_SRAM1.D10: U8.D26 U14.31 | length 771
  Top Layer w4: U8.D26@5882.13,4564.02 5910,4564.02 5920,4564.02 5924.74,4564.02 5936.99,4564.02 5948.96,4552.04 5967.19,4552.04 6015.19,4600.04 6015.19,4625.04 6065.19,4675.04 6065.19,4713.71 v1(6045.52,4733.37) ; U8.D26@5887.32,4558.82 cw(c5899.85,4546.29) 5899.85,4564.02 cw(c5899.85,4581.74) U8.D26@5887.32,4569.21 ; U8.D26@5887.43,4558.71 cw(c5900.23,4545.91) 5900.23,4564.02 cw(c5900.23,4582.12) U8.D26@5887.43,4569.32 ; v1@6045.52,4723.87 cw(c6045.52,4700.94) 6061.74,4717.16 cw(c6077.96,4733.37) v1@6055.02,4733.37 ; v1@6045.52,4727.87 cw(c6045.52,4714.6) 6054.91,4723.99 cw(c6064.3,4733.37) v1@6051.02,4733.37
  Bottom Layer w4: v1@6045.52,4723.87 cw(c6045.52,4700.94) 6061.74,4717.16 cw(c6077.96,4733.37) v1@6055.02,4733.37 ; v1@6045.52,4727.87 cw(c6045.52,4714.6) 6054.91,4723.99 cw(c6064.3,4733.37) v1@6051.02,4733.37 ; v1(6045.52,4733.37) 6100.86,4678.04 6100.86,4629.14 6130,4600 6130,4575 6143.74,4561.26 U14.31@6170.59,4561.26 ; 6134.65,4570.35 ccw(c6143.3,4579.01) U14.31@6149.19,4568.27 ; 6138.42,4566.58 ccw(c6145.97,4574.14) U14.31@6151.11,4564.77 ; 6142.19,4562.81 ccw(c6148.65,4569.26) U14.31@6153.03,4561.26
DB_SRAM1.D11: U8.D24 U14.32 | length 881.1
  Top Layer w4: v1(5992.86,4604.04) 5980.52,4591.71 5944.19,4591.71 5940.36,4587.88 5924.74,4587.88 5920,4587.88 5910,4587.88 5843.27,4587.88 ; 5815.92,4576.55 cw(c5843.27,4549.2) 5843.27,4587.88 ; 5815.92,4576.55 cw(c5843.27,4549.2) 5843.27,4587.88 ; 5815.92,4576.55 cw(c5803.39,4589.08) 5803.39,4571.36 ccw(c5803.39,4589.08) 5815.92,4576.55 ; 5815.92,4576.55 ccw(c5828.45,4564.02) 5810.73,4564.02 cw(c5828.45,4564.02) 5815.92,4576.55
  MidLayer2 w4: v1(5992.86,4604.04) 6015.86,4627.04 6065.19,4627.04 6070.52,4621.71 6277.52,4621.71 6281.86,4626.04 v1(6281.86,4641.71) ; v1@5992.86,4609.54 ccw(c5992.86,4622.82) 6002.25,4613.43 ccw(c6011.64,4604.04) v1@5998.36,4604.04 ; v1@5992.86,4613.54 ccw(c5992.86,4636.48) 6009.07,4620.26 ccw(c6025.29,4604.04) v1@6002.36,4604.04
  Bottom Layer w4: U14.32@6170.59,4592.75 6230.9,4592.75 6257.75,4592.75 6281.86,4616.86 v1(6281.86,4641.71) ; U14.32@6193.81,4587.1 cw(c6207.46,4573.44) 6207.46,4592.75 cw(c6207.46,4612.07) U14.32@6193.81,4598.41 ; v1@6275.14,4634.99 cw(c6258.92,4618.77) 6281.86,4618.77 cw(c6304.79,4618.77) v1@6288.57,4634.99 ; v1@6277.97,4637.82 cw(c6268.58,4628.43) 6281.86,4628.43 cw(c6295.14,4628.43) v1@6285.75,4637.82
DB_SRAM1.D12: U8.H10 U14.35 | length 3952.9
  Top Layer w4: v3(5232.52,4426.22) U8.H10@5252.2,4406.54 ; U8.H10@5244.7,4406.54 ccw(c5226.6,4406.54) 5239.4,4419.34 ccw(c5252.2,4432.14) U8.H10@5252.2,4414.04 ; U8.H10@5244.86,4406.54 ccw(c5227.14,4406.54) 5239.67,4419.07 ccw(c5252.2,4431.6) U8.H10@5252.2,4413.88 ; 5245.32,4413.42 cw(c5258.13,4426.22) 5240.02,4426.22 ccw(c5258.13,4426.22) 5245.32,4413.42 ; 5245.32,4413.42 ccw(c5232.52,4400.61) 5232.52,4418.72 cw(c5232.52,4400.61) 5245.32,4413.42
  MidLayer2 w4: 5208.66,4699.16 5208.66,4640.9 ; v3@5225.05,4426.87 ccw(c5207.01,4428.45) 5220.88,4440.09 ; v3@5233.17,4433.69 cw(c5234.75,4451.73) 5220.88,4440.09 ; v1(6256.86,4766.71) 6273.52,4783.37 6365.19,4783.37 6431.86,4850.04 v1(6473.52,4850.04) ; v1@6256.86,4772.21 ccw(c6256.86,4785.49) 6266.25,4776.1 ccw(c6275.64,4766.71) v1@6262.36,4766.71 ; v1@6256.86,4776.21 ccw(c6256.86,4799.14) 6273.07,4782.93 ccw(c6289.29,4766.71) v1@6266.36,4766.71 ; v1@6466.81,4843.32 ccw(c6450.59,4827.11) 6450.59,4850.04 ccw(c6450.59,4872.98) v1@6466.81,4856.76 ; v1@6469.64,4846.15 ccw(c6460.25,4836.76) 6460.25,4850.04 ccw(c6460.25,4863.32) v1@6469.64,4853.93 ; v1(6506.86,4941.71) 6533.86,4941.71 6548.52,4956.37 6548.52,5000.04 6465.19,5083.37 6465.19,5166.71 6448.52,5183.37 5768.86,5183.37 5743.86,5158.37 5702.56,5158.37 5639.56,5221.37 5519.86,5221.37 5473.52,5175.04 5473.52,5157.37 5480.86,5150.04 5573.52,5150.04 5583.48,5160 5610,5160 5623.52,5146.48 5623.52,5125.04 5615.19,5116.71 5598.52,5116.71 5581.86,5133.37 5465.19,5133.37 5423.52,5091.71 5406.86,5091.71 5332.15,5017 5178.31,5017 5061.69,4900.37 5054.52,4900.37 5036.19,4882.04 5036.19,4826.44 5070.59,4792.04 5195.21,4792.04 5208.66,4778.59 5208.66,4720 5208.66,4710 5208.66,4640.9 ; v1@6510.75,4937.82 cw(c6520.14,4928.43) 6520.14,4941.71 cw(c6520.14,4954.99) v1@6510.75,4945.6 ; v1@6513.57,4934.99 cw(c6529.79,4918.77) 6529.79,4941.71 cw(c6529.79,4964.64) v1@6513.57,4948.43 ; 5208.66,4640.9 5208.66,4582.64 5208.66,4563.22 5208.66,4489.1 5208.66,4469.6 ccw(c5250.39,4469.6) 5220.88,4440.09
  Bottom Layer w4: U14.35@6193.81,4681.59 cw(c6207.46,4667.93) 6207.46,4687.24 cw(c6207.46,4706.56) U14.35@6193.81,4692.9 ; v1@6250.14,4759.99 cw(c6233.92,4743.77) 6256.86,4743.77 cw(c6279.79,4743.77) v1@6263.57,4759.99 ; v1@6252.97,4762.82 cw(c6243.58,4753.43) 6256.86,4753.43 cw(c6270.14,4753.43) v1@6260.75,4762.82 ; v1(6256.86,4766.71) 6256.86,4704.1 6240,4687.24 U14.35@6171.47,4687.24 ; v1(6473.52,4850.04) 6506.86,4883.37 v1(6506.86,4941.71) ; v1@6473.52,4855.54 ccw(c6473.52,4868.82) 6482.91,4859.43 ccw(c6492.3,4850.04) v1@6479.02,4850.04 ; v1@6473.52,4859.54 ccw(c6473.52,4882.48) 6489.74,4866.26 ccw(c6505.96,4850.04) v1@6483.02,4850.04 ; v1@6500.14,4934.99 cw(c6483.92,4918.77) 6506.86,4918.77 cw(c6529.79,4918.77) v1@6513.57,4934.99 ; v1@6502.97,4937.82 cw(c6493.58,4928.43) 6506.86,4928.43 cw(c6520.14,4928.43) v1@6510.75,4937.82 ; U14.35@6171.47,4687.24 U14.35@6170.59,4687.24 U14.35@6171.47,4687.24
DB_SRAM1.D13: U8.B18 U14.36 | length 2184.8
  Top Layer w4: U8.B18@5567.17,4650.1 ccw(c5567.17,4667.83) 5579.7,4655.29 ; U8.B18@5574.51,4642.76 cw(c5592.23,4642.76) 5579.7,4655.29 ; v1@5712.69,5110.71 ccw(c5689.76,5110.71) 5705.97,5126.93 ccw(c5722.19,5143.14) v1@5722.19,5120.21 ; v1@5716.69,5110.71 ccw(c5703.41,5110.71) 5712.8,5120.1 ccw(c5722.19,5129.49) v1@5722.19,5116.21 ; v1(5722.19,5110.71) 5691.19,5141.71 5655.19,5141.71 5640.19,5126.71 5640.19,5075.04 5665.19,5050.04 5665.19,4959.71 5656.86,4951.37 5627.52,4951.37 5623.52,4947.37 5623.52,4829.37 5582.67,4788.52 5582.67,4724.74 5582.67,4720 5582.67,4710 5582.67,4662.47 cw(c5572.52,4662.47) 5579.7,4655.29
  MidLayer2 w4: v1@5714.51,5105.12 ccw(c5703.52,5097.12) 5703.52,5110.71 ; v1@5714.51,5116.3 cw(c5703.52,5124.29) 5703.52,5110.71 ; v1(5722.19,5110.71) 5703.52,5110.71 ; v1@6316.81,4856.76 ccw(c6300.59,4872.98) 6323.52,4872.98 ccw(c6346.46,4872.98) v1@6330.24,4856.76 ; v1@6319.64,4853.93 ccw(c6310.25,4863.32) 6323.52,4863.32 ccw(c6336.8,4863.32) v1@6327.41,4853.93 ; v1(6323.52,4850.04) 6323.52,4928.04 6305.77,4945.8 6305.77,4973.15 6195.21,5083.71 6007.19,5083.71 5965.19,5041.71 5598.52,5041.71 5581.86,5058.37 5581.86,5075.04 5590.19,5083.37 5676.19,5083.37 5703.52,5110.71
  Bottom Layer w4: U14.36@6170.59,4718.74 6200.55,4718.74 ; U14.36@6195.44,4715.44 cw(c6200.55,4713.12) 6200.55,4718.74 ; U14.36@6195.44,4722.04 ccw(c6200.55,4724.36) 6200.55,4718.74 ; v1(6323.52,4850.04) 6308.56,4865 6255,4865 6235,4845 6235,4753.18 6231.86,4750.04 6200.55,4718.74
DB_SRAM1.D14: U8.E21 U14.37 | length 1194
  Top Layer w4: U8.E21@5685.28,4524.65 v3(5704.96,4544.33) ; U8.E21@5685.28,4531.99 ccw(c5685.28,4549.71) 5697.81,4537.18 ccw(c5710.34,4524.65) U8.E21@5692.62,4524.65 ; U8.E21@5685.28,4532.15 ccw(c5685.28,4550.25) 5698.08,4537.45 ccw(c5710.88,4524.65) U8.E21@5692.78,4524.65 ; 5692.16,4531.53 cw(c5704.96,4518.72) 5704.96,4536.83 ccw(c5704.96,4518.72) 5692.16,4531.53 ; 5692.16,4531.53 ccw(c5679.35,4544.33) 5697.46,4544.33 cw(c5679.35,4544.33) 5692.16,4531.53
  MidLayer1 w4: v3@5703.66,4551.72 ccw(c5700.51,4569.55) 5715.35,4559.16 ccw(c5730.18,4548.78) v3@5712.35,4545.63 ; 5715.38,4559.19 ccw(c5687.34,4576.84) 5720.47,4577.01 5720.47,4661.38 5720.47,4710 5720.47,4810.67 5732.35,4822.56 5732.35,4827.53 5731.52,4828.35 5731.52,4843.73 5768.5,4880.71 5875.5,4880.71 5885.17,4890.37 5903.56,4890.37 5909.44,4884.5 5930.56,4884.5 5936.44,4890.37 5937.19,4890.37 6094.19,4733.37 6098.52,4733.37 v1(6099.52,4734.37) ; 6072.49,4755.07 ccw(c6099.52,4782.1) v1@6099.52,4743.87 ; 6079.32,4748.24 ccw(c6099.52,4768.44) v1@6099.52,4739.87 ; 6086.15,4741.41 ccw(c6099.52,4754.79) v1@6099.52,4735.87 ; 6087.79,4739.78 cw(c6082.38,4734.37) v1@6090.02,4734.37
  Bottom Layer w4: v1(6099.52,4734.37) 6126.19,4734.37 6141.86,4750.04 6170.59,4750.04 6173.52,4750.04 6173.52,4750.23 U14.37@6170.59,4750.23 ; v1@6103.41,4730.49 cw(c6112.8,4721.1) 6112.8,4734.37 cw(c6112.8,4747.65) v1@6103.41,4738.26 ; v1@6106.24,4727.66 cw(c6122.46,4711.44) 6122.46,4734.37 cw(c6122.46,4757.31) v1@6106.24,4741.09 ; 6127.51,4735.7 cw(c6152.95,4710.25) U14.37@6153.02,4746.23 ; 6134.32,4742.51 cw(c6152.98,4723.85) U14.37@6153.03,4750.23 ; 6141.13,4749.32 cw(c6153.01,4737.44) U14.37@6153.04,4754.23
DB_SRAM1.D15: U8.F19 U14.38 | length 1237.1
  Top Layer w4: U8.F19@5606.54,4485.28 v3(5626.22,4504.96) ; U8.F19@5606.54,4492.62 ccw(c5606.54,4510.34) 5619.07,4497.81 ccw(c5631.6,4485.28) U8.F19@5613.88,4485.28 ; U8.F19@5606.54,4492.78 ccw(c5606.54,4510.88) 5619.34,4498.08 ccw(c5632.14,4485.28) U8.F19@5614.04,4485.28 ; 5613.42,4492.16 cw(c5626.22,4479.35) 5626.22,4497.46 ccw(c5626.22,4479.35) 5613.42,4492.16 ; 5613.42,4492.16 ccw(c5600.61,4504.96) 5618.72,4504.96 cw(c5600.61,4504.96) 5613.42,4492.16
  MidLayer1 w4: v3@5625.57,4512.43 ccw(c5623.99,4530.47) 5637.86,4518.83 ; v3@5633.69,4505.61 cw(c5651.73,4507.19) 5637.86,4518.83 ; 5650.08,4581.77 5650.08,4567.84 ; v1@6073.77,4786.73 ccw(c6064.86,4781.25) 6064.86,4791.71 ; v1@6073.77,4796.69 cw(c6064.86,4802.17) 6064.86,4791.71 ; v1(6081.86,4791.71) 6064.86,4791.71 ; 5637.86,4518.83 ccw(c5608.35,4548.34) 5650.08,4548.34 5650.08,4567.84 ; 5650.08,4567.84 5650.08,4641.96 5650.08,4661.38 5650.08,4710 5650.08,4720 5650.08,4724.74 5650.08,4835.93 5735.15,4921 5749.82,4921 5795.52,4966.71 5892.37,4966.71 5913.81,4945.26 5913.81,4942.75 6064.86,4791.71
  Bottom Layer w4: v1(6081.86,4791.71) 6089.52,4791.71 6099.5,4781.73 U14.38@6170.59,4781.73 ; v1@6082.29,4790.27 cw(c6085.65,4779.13) 6093.87,4787.36 ; v1@6083.44,4786.44 cw(c6087.83,4771.86) 6098.6,4782.63 ; U14.38@6147.37,4776.07 ccw(c6133.72,4762.42) 6133.72,4781.73 ccw(c6133.72,4801.04) U14.38@6147.37,4787.39
DB_SRAM1.NBHE: U8.G15 U14.40 | length 1673.3
  Top Layer w4: U8.G15@5449.06,4445.91 v3(5468.74,4465.59) ; U8.G15@5449.06,4453.25 ccw(c5449.06,4470.97) 5461.59,4458.44 ccw(c5474.12,4445.91) U8.G15@5456.4,4445.91 ; U8.G15@5449.06,4453.41 ccw(c5449.06,4471.51) 5461.86,4458.71 ccw(c5474.66,4445.91) U8.G15@5456.56,4445.91 ; 5455.94,4452.79 cw(c5468.74,4439.98) 5468.74,4458.09 ccw(c5468.74,4439.98) 5455.94,4452.79 ; 5455.94,4452.79 ccw(c5443.13,4465.59) 5461.24,4465.59 cw(c5443.13,4465.59) 5455.94,4452.79
  MidLayer2 w4: v3@5468.09,4473.06 ccw(c5466.51,4491.1) 5480.38,4479.46 ccw(c5494.25,4467.82) v3@5476.21,4466.24 ; 5480.13,4479.17 ccw(c5470.2,4489.1) 5484.25,4489.1 ; 5484.25,4503.03 5484.25,4489.1 ; 5484.25,4699.16 5484.25,4640.9 ; v1@6114.02,4850.04 ccw(c6091.09,4850.04) 6107.31,4866.26 ccw(c6123.52,4882.48) v1@6123.52,4859.54 ; v1@6118.02,4850.04 ccw(c6104.75,4850.04) 6114.14,4859.43 ccw(c6123.52,4868.82) v1@6123.52,4855.54 ; v1(6123.52,4850.04) 6098.52,4875.04 6059.19,4875.04 5967.02,4967.21 5829.63,4967.21 5804.13,4941.71 5674.67,4941.71 5665,4951.37 5633.52,4951.37 5623.52,4941.37 5623.52,4925.37 5633.52,4915.37 5664.52,4915.37 5668.52,4911.37 5668.52,4879.69 5605.54,4816.71 5585.19,4816.71 5568.52,4833.37 5513.52,4833.37 5484.25,4804.1 5484.25,4724.74 5484.25,4720 5484.25,4710 5484.25,4640.9 ; 5484.25,4489.1 5484.25,4582.64 5484.25,4640.9
  Bottom Layer w4: v1(6123.52,4850.04) 6128.84,4844.72 U14.40@6170.59,4844.72 ; v1@6124.58,4851.1 ccw(c6139.98,4866.5) 6139.98,4844.72 ; v1@6127.41,4853.93 ccw(c6149.64,4876.16) U14.40@6149.64,4844.72 ; v1@6130.24,4856.76 ccw(c6159.3,4885.81) U14.40@6159.3,4844.72 ; U14.40@6147.37,4839.07 ccw(c6133.72,4825.41) 6133.72,4844.72 ccw(c6133.72,4864.04) U14.40@6147.37,4850.38
DB_SRAM1.NBLE: U8.E17 U14.39 | length 1391.4
  Top Layer w4: U8.E17@5527.8,4524.65 v3(5547.48,4544.33) ; U8.E17@5527.8,4531.99 ccw(c5527.8,4549.71) 5540.33,4537.18 ccw(c5552.86,4524.65) U8.E17@5535.14,4524.65 ; U8.E17@5527.8,4532.15 ccw(c5527.8,4550.25) 5540.6,4537.45 ccw(c5553.4,4524.65) U8.E17@5535.3,4524.65 ; 5534.68,4531.53 cw(c5547.48,4518.72) 5547.48,4536.83 ccw(c5547.48,4518.72) 5534.68,4531.53 ; 5534.68,4531.53 ccw(c5521.87,4544.33) 5539.98,4544.33 cw(c5521.87,4544.33) 5534.68,4531.53
  MidLayer1 w4: v3@5546.83,4551.8 ccw(c5545.25,4569.84) 5559.12,4558.2 ccw(c5572.99,4546.56) v3@5554.95,4544.98 ; 5558.87,4557.91 ccw(c5548.94,4567.84) 5562.99,4567.84 ; 5562.99,4581.77 5562.99,4567.84 ; v1@6046.36,4841.71 ccw(c6023.42,4841.71) 6039.64,4857.93 ccw(c6055.86,4874.14) v1@6055.86,4851.21 ; v1@6050.36,4841.71 ccw(c6037.08,4841.71) 6046.47,4851.1 ccw(c6055.86,4860.49) v1@6055.86,4847.21 ; v1(6055.86,4841.71) 5905.86,4991.71 5652.72,4991.71 5623.02,4962.01 5623.02,4826.69 5562.99,4766.65 5562.99,4724.74 5562.99,4720 5562.99,4710 5562.99,4661.38 5562.99,4567.84
  Bottom Layer w4: v1@6055.86,4832.21 cw(c6055.86,4809.27) 6072.07,4825.49 cw(c6088.29,4841.71) v1@6065.36,4841.71 ; v1@6055.86,4836.21 cw(c6055.86,4822.93) 6065.25,4832.32 cw(c6074.64,4841.71) v1@6061.36,4841.71 ; v1(6055.86,4841.71) 6084.34,4813.23 U14.39@6170.59,4813.23 ; U14.39@6147.37,4807.57 ccw(c6133.72,4793.91) 6133.72,4813.23 ccw(c6133.72,4832.54) U14.39@6147.37,4818.88
DB_SRAM1.NCS: U8.C20 U14.6 | length 1745.1
  Top Layer w4: 5669.77,4724.74 5669.77,4725.04 ; v1@5682.69,4819.71 cw(c5659.76,4819.71) 5675.97,4803.49 cw(c5692.19,4787.27) v1@5692.19,4810.21 ; v1@5686.69,4819.71 cw(c5673.41,4819.71) 5682.8,4810.32 cw(c5692.19,4800.93) v1@5692.19,4814.21 ; v1(5692.19,4819.71) 5673.52,4801.04 5673.52,4769 5673.52,4752.93 5669.77,4749.17 5669.77,4746.65 5669.77,4738 5669.77,4720 5669.77,4710 5669.77,4643.27 ; 5658.44,4615.92 ccw(c5631.09,4643.27) 5669.77,4643.27 ; 5658.44,4615.92 ccw(c5631.09,4643.27) 5669.77,4643.27 ; 5658.44,4615.92 ccw(c5670.97,4603.39) 5653.25,4603.39 cw(c5670.97,4603.39) 5658.44,4615.92 ; 5658.44,4615.92 cw(c5645.91,4628.45) 5645.91,4610.73 ccw(c5645.91,4628.45) 5658.44,4615.92
  MidLayer2 w4: v1@5685.47,4826.43 ccw(c5669.26,4842.64) 5692.19,4842.64 ccw(c5715.13,4842.64) v1@5698.91,4826.43 ; v1@5688.3,4823.6 ccw(c5678.91,4832.99) 5692.19,4832.99 ccw(c5705.47,4832.99) v1@5696.08,4823.6 ; v1(5692.19,4819.71) 5692.19,4858.1 5717.47,4883.37 5832.23,4883.37 5848.9,4866.71 5863.48,4866.71 ; v1@6531.47,4784.99 ccw(c6515.26,4768.77) 6515.26,4791.71 ccw(c6515.26,4814.64) v1@6531.47,4798.43 ; v1@6534.3,4787.82 ccw(c6524.91,4778.43) 6524.91,4791.71 ccw(c6524.91,4804.99) v1@6534.3,4795.6 ; v1(6538.19,4791.71) 6501.86,4791.71 6418.52,4708.37 6081.19,4708.37 6065.19,4724.37 6065.19,4743.37 5999.19,4809.37 5920.81,4809.37 ; 5863.48,4866.71 5877.81,4852.38 ; 5863.48,4866.71 5877.81,4852.38 ; 5877.81,4852.38 5920.81,4809.37 ; 5877.81,4852.38 5877.81,4851.44 5919.88,4809.37 5920.81,4809.37
  Bottom Layer w4: v1(6538.19,4791.71) 6559.71,4813.23 U14.6@6619.41,4813.23 ; v1@6538.19,4797.21 ccw(c6538.19,4810.49) 6547.58,4801.1 ccw(c6556.97,4791.71) v1@6543.69,4791.71 ; v1@6538.19,4801.21 ccw(c6538.19,4824.14) 6554.41,4807.93 ccw(c6570.63,4791.71) v1@6547.69,4791.71 ; U14.6@6596.19,4807.57 ccw(c6582.54,4793.91) 6582.54,4813.23 ccw(c6582.54,4832.54) U14.6@6596.19,4818.88
DB_SRAM1.NOE: U8.E14 U14.41 | length 1760.3
  Top Layer w4: U8.E14@5409.69,4524.65 v3(5429.37,4544.33) ; U8.E14@5409.69,4531.99 ccw(c5409.69,4549.71) 5422.22,4537.18 ccw(c5434.75,4524.65) U8.E14@5417.03,4524.65 ; U8.E14@5409.69,4532.15 ccw(c5409.69,4550.25) 5422.49,4537.45 ccw(c5435.29,4524.65) U8.E14@5417.19,4524.65 ; 5416.57,4531.53 cw(c5429.37,4518.72) 5429.37,4536.83 ccw(c5429.37,4518.72) 5416.57,4531.53 ; 5416.57,4531.53 ccw(c5403.76,4544.33) 5421.87,4544.33 cw(c5403.76,4544.33) 5416.57,4531.53
  MidLayer1 w4: v3@5428.72,4551.8 ccw(c5427.14,4569.84) 5441.01,4558.2 ccw(c5454.88,4546.56) v3@5436.84,4544.98 ; 5440.76,4557.91 ccw(c5430.83,4567.84) 5444.88,4567.84 ; 5444.88,4581.77 5444.88,4567.84 ; v1(5468.4,4898.5) 5433.5,4898.5 5431.86,4896.86 5431.86,4804.73 5444.88,4791.71 5444.88,4724.74 5444.88,4720 5444.88,4710 5444.88,4567.84
  MidLayer2 w4: v1(5789.86,4850.04) 5820.67,4850.04 5855,4815.71 5886.19,4815.71 5918.52,4783.37 v1(5971.86,4783.37) ; v1@5793.75,4846.15 cw(c5803.14,4836.76) 5803.14,4850.04 cw(c5803.14,4863.32) v1@5793.75,4853.93 ; v1@5796.57,4843.32 cw(c5812.79,4827.11) 5812.79,4850.04 cw(c5812.79,4872.98) v1@5796.57,4856.76 ; v1@5965.14,4776.66 ccw(c5948.92,4760.44) 5948.92,4783.37 ccw(c5948.92,4806.31) v1@5965.14,4790.09 ; v1@5967.97,4779.49 ccw(c5958.58,4770.1) 5958.58,4783.37 ccw(c5958.58,4796.65) v1@5967.97,4787.26
  Bottom Layer w4: v1(5468.4,4898.5) 5545.61,4975.71 5655,4975.71 5699.69,4975.71 5789.86,4885.54 v1(5789.86,4850.04) ; v1@5468.4,4904 ccw(c5468.4,4917.28) 5477.79,4907.89 ccw(c5487.18,4898.5) v1@5473.9,4898.5 ; v1@5468.4,4908 ccw(c5468.4,4930.94) 5484.62,4914.72 ccw(c5500.83,4898.5) v1@5477.9,4898.5 ; v1@5783.14,4856.76 ccw(c5766.92,4872.98) 5789.86,4872.98 ccw(c5812.79,4872.98) v1@5796.57,4856.76 ; v1@5785.97,4853.93 ccw(c5776.58,4863.32) 5789.86,4863.32 ccw(c5803.14,4863.32) v1@5793.75,4853.93 ; v1(5971.86,4783.37) 6031.86,4843.37 6031.86,4854.37 6053.7,4876.22 U14.41@6170.59,4876.22 ; v1@5971.86,4788.87 ccw(c5971.86,4802.15) 5981.25,4792.76 ccw(c5990.64,4783.37) v1@5977.36,4783.37 ; v1@5971.86,4792.87 ccw(c5971.86,4815.81) 5988.07,4799.59 ccw(c6004.29,4783.37) v1@5981.36,4783.37 ; U14.41@6147.37,4870.56 ccw(c6133.72,4856.9) 6133.72,4876.22 ccw(c6133.72,4895.53) U14.41@6147.37,4881.88
DB_SRAM1.NWE: U8.J20 U14.17 | length 1294.7
  Top Layer w4: U8.J20@5645.91,4367.17 v3(5665.59,4386.85) ; U8.J20@5645.91,4374.51 ccw(c5645.91,4392.23) 5658.44,4379.7 ccw(c5670.97,4367.17) U8.J20@5653.25,4367.17 ; U8.J20@5645.91,4374.67 ccw(c5645.91,4392.77) 5658.71,4379.97 ccw(c5671.51,4367.17) U8.J20@5653.41,4367.17 ; 5652.79,4374.05 cw(c5665.59,4361.24) 5665.59,4379.35 ccw(c5665.59,4361.24) 5652.79,4374.05 ; 5652.79,4374.05 ccw(c5639.98,4386.85) 5658.09,4386.85 cw(c5639.98,4386.85) 5652.79,4374.05
  MidLayer2 w4: v3@5666.24,4394.32 ccw(c5667.82,4412.36) 5679.46,4398.49 ccw(c5691.1,4384.62) v3@5673.06,4386.2 ; 5679.17,4398.24 cw(c5689.1,4388.31) 5689.1,4402.36 5782.64,4402.36 5910,4402.36 5920,4402.36 5966.58,4402.36 5968.9,4400.04 6040.19,4400.04 6050.86,4389.37 6123.52,4389.37 6134.88,4389.37 6145.54,4400.04 6263.17,4400.04 6276.84,4386.37 6369.86,4386.37 v1(6441.86,4458.37) ; v1@6432.36,4458.37 cw(c6409.42,4458.37) 6425.64,4442.16 cw(c6441.86,4425.94) v1@6441.86,4448.87 ; v1@6436.36,4458.37 cw(c6423.08,4458.37) 6432.47,4448.99 cw(c6441.86,4439.6) v1@6441.86,4452.87
  Bottom Layer w4: v1(6441.86,4458.37) 6459.52,4476.04 6619.41,4476.04 6623.52,4476.04 6623.52,4466.77 U14.17@6619.41,4466.77 ; v1@6441.86,4463.87 ccw(c6441.86,4477.15) 6451.25,4467.76 ccw(c6460.64,4458.37) v1@6447.36,4458.37 ; v1@6441.86,4467.87 ccw(c6441.86,4490.81) 6458.08,4474.59 ccw(c6474.29,4458.37) v1@6451.36,4458.37
DB_SRAM2.A0: U8.D16 U15.1 | length 2551.1
  Top Layer w4: U8.D16@5488.43,4564.02 v3(5508.11,4583.7) ; U8.D16@5488.43,4571.36 ccw(c5488.43,4589.08) 5500.96,4576.55 ccw(c5513.49,4564.02) U8.D16@5495.77,4564.02 ; U8.D16@5488.43,4571.52 ccw(c5488.43,4589.62) 5501.23,4576.82 ccw(c5514.03,4564.02) U8.D16@5495.93,4564.02 ; 5495.31,4570.9 cw(c5508.11,4558.09) 5508.11,4576.2 ccw(c5508.11,4558.09) 5495.31,4570.9 ; 5495.31,4570.9 ccw(c5482.5,4583.7) 5500.61,4583.7 cw(c5482.5,4583.7) 5495.31,4570.9
  MidLayer1 w4: v3@5502.81,4589 ccw(c5490,4601.81) 5508.11,4601.81 ccw(c5526.22,4601.81) v3@5513.41,4589 ; v3@5502.92,4588.89 ccw(c5490.38,4601.43) 5508.11,4601.43 ccw(c5525.84,4601.43) v3@5513.3,4588.89 ; v3(5508.11,4583.7) 5508.11,4661.38 5508.11,4710 5508.11,4720 5508.11,4724.74 5508.11,4809.63 5606.86,4908.37 5606.86,4968.47 5646.76,5008.37 5918.17,5008.37 6009.84,5100.04 6526.5,5100.04 6543.17,5116.71 6659.84,5116.71 6726.5,5050.04 6834.84,5050.04 6869.17,5015.71 6917.17,5015.71 6934.84,5033.37 7090.19,5033.37 7139.69,4983.87 7265.69,4983.87 ; v1@7272.36,5000.02 cw(c7249.6,4999.97) 7265.69,4983.88 ; v1@7276.36,5000.03 cw(c7263.18,5000) 7272.5,4990.68 cw(c7281.81,4981.37) v1@7281.84,4994.54 ; v1@7281.84,4990.54 ccw(c7281.78,4967.78) 7265.69,4983.88 ; v1(7281.86,5000.04) 7265.69,4983.87
  Bottom Layer w4: v1(7281.86,5000.04) 7294.41,4987.49 ; U15.1@7289.37,4976.92 ccw(c7280.81,4987.49) 7294.41,4987.49 ; U15.1@7294.41,4970.71 7294.41,4987.49 ; U15.1@7299.45,4976.92 cw(c7308.01,4987.49) 7294.41,4987.49
DB_SRAM2.A1: U8.D18 U15.2 | length 2552.2
  Top Layer w4: U8.D18@5567.17,4564.02 v3(5586.85,4583.7) ; U8.D18@5567.17,4571.36 ccw(c5567.17,4589.08) 5579.7,4576.55 ccw(c5592.23,4564.02) U8.D18@5574.51,4564.02 ; U8.D18@5567.17,4571.52 ccw(c5567.17,4589.62) 5579.97,4576.82 ccw(c5592.77,4564.02) U8.D18@5574.67,4564.02 ; 5574.05,4570.9 cw(c5586.85,4558.09) 5586.85,4576.2 ccw(c5586.85,4558.09) 5574.05,4570.9 ; 5574.05,4570.9 ccw(c5561.24,4583.7) 5579.35,4583.7 cw(c5561.24,4583.7) 5574.05,4570.9
  MidLayer1 w4: v3@5581.55,4589 ccw(c5568.74,4601.81) 5586.85,4601.81 ccw(c5604.96,4601.81) v3@5592.15,4589 ; v3@5581.66,4588.89 ccw(c5569.12,4601.43) 5586.85,4601.43 ccw(c5604.58,4601.43) v3@5592.04,4588.89 ; v3(5586.85,4583.7) 5586.85,4661.38 5586.85,4710 5586.85,4720 5586.85,4724.74 5586.85,4767.89 5640.19,4821.22 5640.19,4841.71 5674.52,4876.04 5674.52,4920 5696.23,4941.71 5740.19,4941.71 v1(5761.52,4963.04) ; v1@5752.02,4963.04 cw(c5729.09,4963.04) 5745.31,4946.82 cw(c5761.52,4930.61) v1@5761.52,4953.54 ; v1@5756.02,4963.04 cw(c5742.75,4963.04) 5752.13,4953.65 cw(c5761.52,4944.26) v1@5761.52,4957.54
  Bottom Layer w4: v1(5761.52,4963.04) 5883.54,4963.04 6031.95,5111.44 6036.88,5116.37 6514.86,5116.37 6574.52,5176.04 6829.9,5176.04 6855.9,5150.04 6915.19,5150.04 6923.52,5141.71 7139.58,5141.71 7259.19,5022.1 7259.19,4946.21 7266.19,4939.21 U15.2@7294.41,4939.21 ; v1@5765.41,4959.15 cw(c5774.8,4949.76) 5774.8,4963.04 cw(c5774.8,4976.32) v1@5765.41,4966.93 ; v1@5768.24,4956.32 cw(c5784.46,4940.11) 5784.46,4963.04 cw(c5784.46,4985.98) v1@5768.24,4969.76
DB_SRAM2.A2: U8.A20 U15.3 | length 2581
  Top Layer w4: U8.A20@5640.6,4687.43 ccw(c5627.8,4700.23) 5645.91,4700.23 ccw(c5664.01,4700.23) U8.A20@5651.21,4687.43 ; U8.A20@5645.91,4682.13 5645.91,4710 5645.91,4720 5645.91,4747.94 5656.86,4758.89 5656.86,4768 5656.86,4839.23 5719.52,4901.9 5719.52,5026.71 5745,5052.18 5745,5135.85 5759.19,5150.04 v1(5799.86,5150.04) ; v1@5793.14,5143.32 ccw(c5776.92,5127.11) 5776.92,5150.04 ccw(c5776.92,5172.98) v1@5793.14,5156.76 ; v1@5795.97,5146.15 ccw(c5786.58,5136.76) 5786.58,5150.04 ccw(c5786.58,5163.32) v1@5795.97,5153.93 ; 5645.91,4699.85 ccw(c5663.63,4699.85) 5651.1,4687.32 cw(c5663.63,4699.85) 5645.91,4699.85 ; 5645.91,4699.85 cw(c5628.18,4699.85) 5640.71,4687.32 ccw(c5628.18,4699.85) 5645.91,4699.85
  MidLayer1 w4: v1(5799.86,5150.04) 5852.52,5202.71 6556.86,5202.71 6575.52,5184.04 7057.52,5184.04 v1(7240.19,5001.37) ; v1@5799.86,5155.54 ccw(c5799.86,5168.82) 5809.25,5159.43 ccw(c5818.64,5150.04) v1@5805.36,5150.04 ; v1@5799.86,5159.54 ccw(c5799.86,5182.48) 5816.07,5166.26 ccw(c5832.29,5150.04) v1@5809.36,5150.04 ; v1@7230.69,5001.37 ccw(c7207.76,5001.37) 7223.97,5017.59 ccw(c7240.19,5033.81) v1@7240.19,5010.87 ; v1@7234.69,5001.37 ccw(c7221.41,5001.37) 7230.8,5010.76 ccw(c7240.19,5020.15) v1@7240.19,5006.87
  Bottom Layer w4: v1@7233.47,4994.66 cw(c7217.26,4978.44) 7240.19,4978.44 cw(c7263.13,4978.44) v1@7246.91,4994.66 ; v1@7236.3,4997.49 cw(c7226.91,4988.1) 7240.19,4988.1 cw(c7253.47,4988.1) v1@7244.08,4997.49 ; v1(7240.19,5001.37) 7240.19,4924.72 7257.19,4907.72 U15.3@7294.41,4907.72 ; U15.3@7271.19,4902.06 ccw(c7257.54,4888.4) 7257.54,4907.72 ccw(c7257.54,4927.03) U15.3@7271.19,4913.37
DB_SRAM2.A3: U8.D20 U15.4 | length 2598.8
  Top Layer w4: U8.D20@5645.91,4564.02 v3(5665.59,4583.7) ; U8.D20@5645.91,4571.36 ccw(c5645.91,4589.08) 5658.44,4576.55 ccw(c5670.97,4564.02) U8.D20@5653.25,4564.02 ; U8.D20@5645.91,4571.52 ccw(c5645.91,4589.62) 5658.71,4576.82 ccw(c5671.51,4564.02) U8.D20@5653.41,4564.02 ; 5652.79,4570.9 cw(c5665.59,4558.09) 5665.59,4576.2 ccw(c5665.59,4558.09) 5652.79,4570.9 ; 5652.79,4570.9 ccw(c5639.98,4583.7) 5658.09,4583.7 cw(c5639.98,4583.7) 5652.79,4570.9
  MidLayer1 w4: v3@5660.4,4588.89 ccw(c5647.86,4601.43) 5665.59,4601.43 ccw(c5683.32,4601.43) v3@5670.78,4588.89 ; 5664,4819.97 5664,4747 5664.03,4726.3 5665.59,4724.74 5665.59,4720 5665.59,4710 5665.59,4661.38 v3(5665.59,4583.7) ; 5664.03,4820 5664.03,4838.57 5738.46,4913 5753.15,4913 5781.86,4941.71 v1(5840.19,4941.71) ; v1@5833.47,4934.99 ccw(c5817.26,4918.77) 5817.26,4941.71 ccw(c5817.26,4964.64) v1@5833.47,4948.43 ; v1@5836.3,4937.82 ccw(c5826.91,4928.43) 5826.91,4941.71 ccw(c5826.91,4954.99) v1@5836.3,4945.6 ; 5665.59,4601.81 cw(c5647.48,4601.81) 5660.29,4589 ccw(c5647.48,4601.81) 5665.59,4601.81 ; 5665.59,4601.81 ccw(c5683.7,4601.81) 5670.89,4589 cw(c5683.7,4601.81) 5665.59,4601.81
  Bottom Layer w4: v1(5840.19,4941.71) 5873.52,4941.71 6040.19,5108.37 6518.17,5108.37 6577.84,5168.04 6826.58,5168.04 6852.92,5141.71 6912.21,5141.71 6920.54,5133.37 7136.6,5133.37 7220,5049.98 7220,4903.74 7247.52,4876.22 U15.4@7294.41,4876.22 ; v1@5844.08,4937.82 cw(c5853.47,4928.43) 5853.47,4941.71 cw(c5853.47,4954.99) v1@5844.08,4945.6 ; v1@5846.91,4934.99 cw(c5863.13,4918.77) 5863.13,4941.71 cw(c5863.13,4964.64) v1@5846.91,4948.43 ; U15.4@7271.19,4870.56 ccw(c7257.54,4856.9) 7257.54,4876.22 ccw(c7257.54,4895.53) U15.4@7271.19,4881.88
